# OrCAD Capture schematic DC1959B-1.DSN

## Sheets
1 PAGE2: size A; title: ULTRALOW NOISE & SPURIOUS FRACTIONAL-N; rev: 1; note: DEMO CIRCUIT 1959B
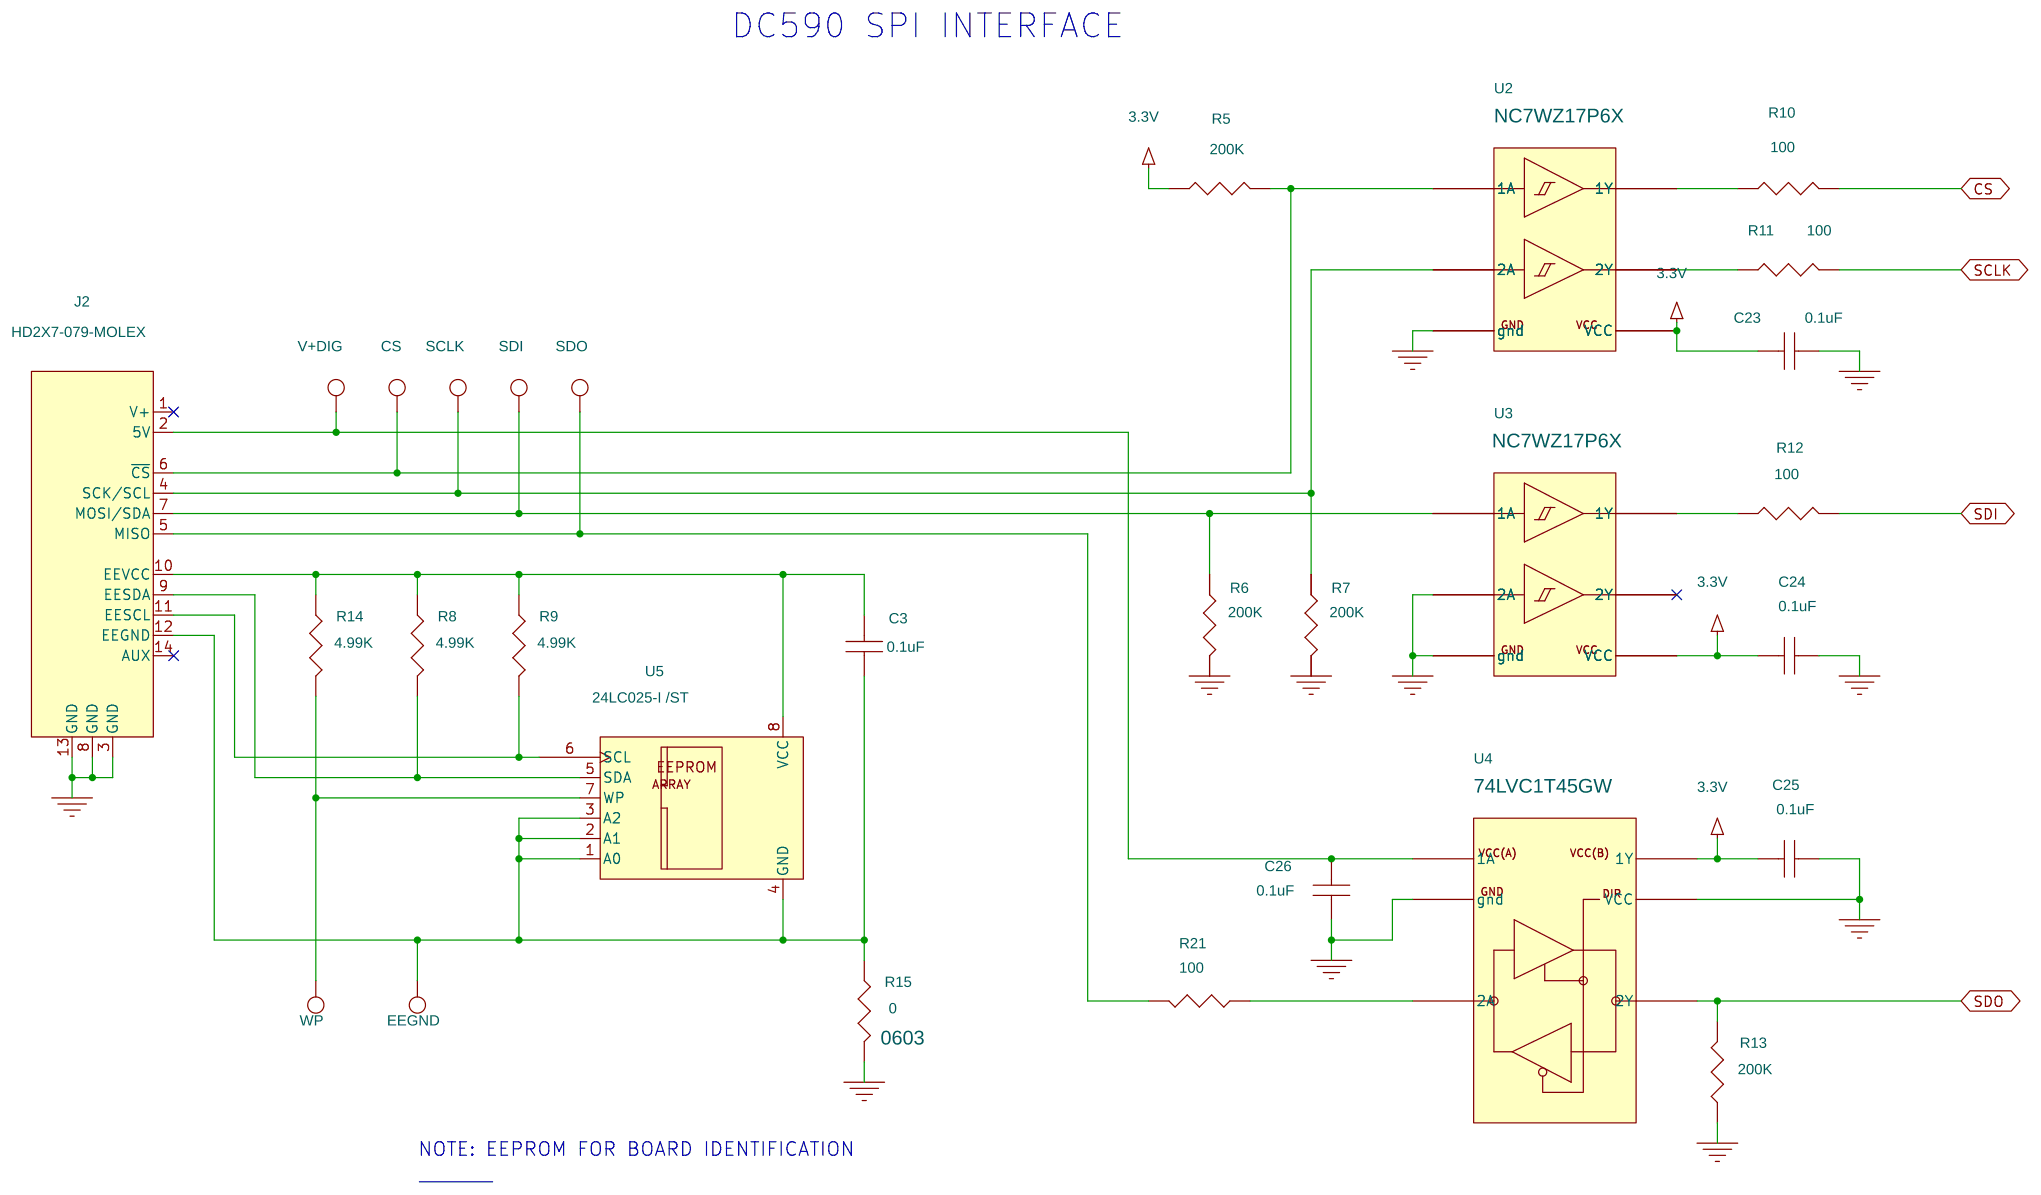
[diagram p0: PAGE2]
2 PAGE1: size Custom
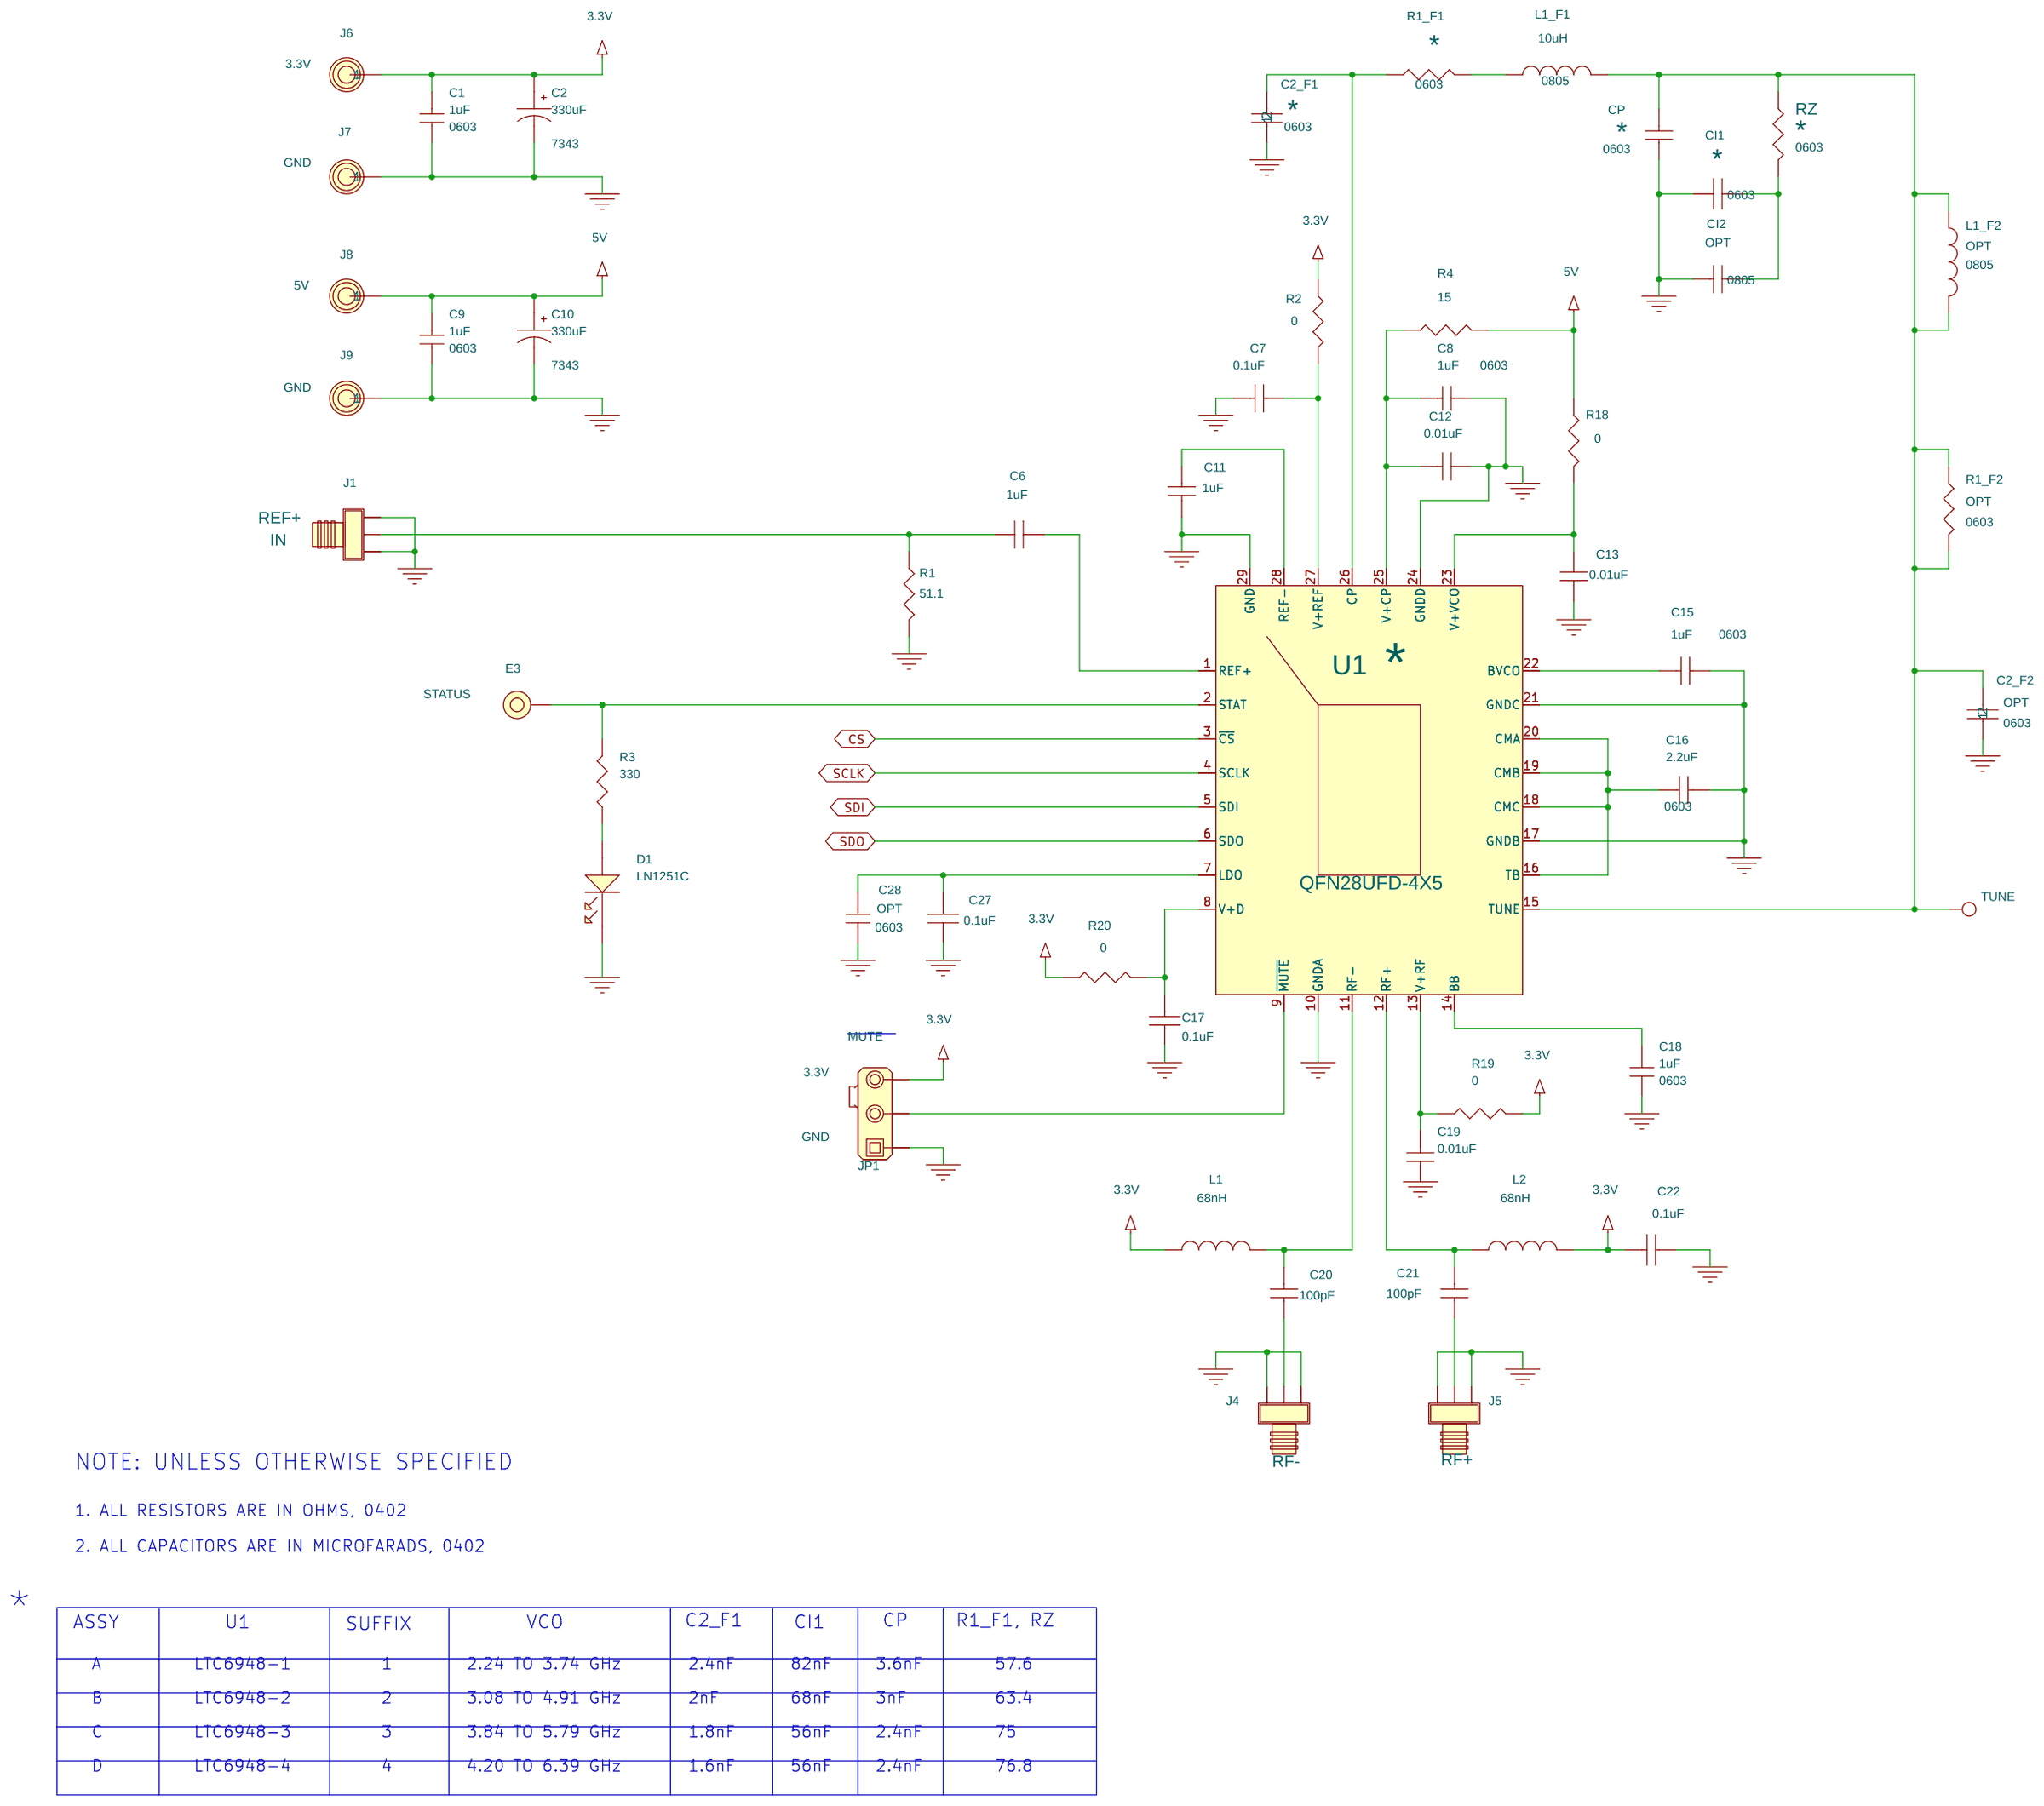
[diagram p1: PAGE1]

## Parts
sheet PAGE1
C1  1uF  [0603]
C2  330uF  [7343]
C2_F1  *  [0603]
C2_F2  OPT  [0603]
C6  1uF  [0402]
C7  0.1uF  [0402]
C8  1uF  [0603]
C9  1uF  [0603]
C10  330uF  [7343]
C11  1uF  [0402]
C12  0.01uF  [0402]
C13  0.01uF  [0402]
C15  1uF  [0603]
C16  2.2uF  [0603]
C17  0.1uF  [0402]
C18  1uF  [0603]
C19  0.01uF  [0402]
C20  100pF  [0402]
C21  100pF  [0402]
C22  0.1uF  [0402]
C27  0.1uF  [0402]
C28  OPT  [0603]
CI1  *  [0603]
CI2  OPT  [0805]
CP  *  [0603]
D1  LN1251C  [LED-LN1251C-RED]
E3  MILLMAX-90  [MILL-MAX-2501]
J1  142-0701-851  [CON-SMA-R]
J4  142-0701-851  [CON-SMA-R]
J5  142-0701-851  [CON-SMA-R]
J6  KEY-575-4  [KEY-575]
J7  KEY-575-4  [KEY-575]
J8  KEY-575-4  [KEY-575]
J9  KEY-575-4  [KEY-575]
JP1  HD1X3-079  [HD1X3-079]
L1  68nH  [0402]
L1_F1  10uH  [0805]
L1_F2  OPT  [0805]
L2  68nH  [0402]
R1  51.1  [0402]
R1_F1  *  [0603]
R1_F2  OPT  [0603]
R2  0  [0402]
R3  330  [0402]
R4  15  [0402]
R18  0  [0402]
R19  0  [0402]
R20  0  [0402]
RZ  *  [0603]
TUNE  TESTPAD-SMD/050SQ/NON/ECO  [TESTPAD-SMD/050SQ/NON/ECO]
U1  *  [QFN28UFD-4X5]
XJP1  2mm Ctrs.
sheet PAGE2
C3  0.1uF  [0402]
C23  0.1uF  [0402]
C24  0.1uF  [0402]
C25  0.1uF  [0402]
C26  0.1uF  [0402]
CS  TESTPAD-SMD/050SQ/NON/ECO  [TESTPAD-SMD/050SQ/NON/ECO]
EEGND  TESTPAD-SMD/050SQ/NON/ECO  [TESTPAD-SMD/050SQ/NON/ECO]
J2  HD2X7-079-MOLEX  [HD2X7-079-MOLEX]
R5  200K  [0402]
R6  200K  [0402]
R7  200K  [0402]
R8  4.99K  [0402]
R9  4.99K  [0402]
R10  100  [0402]
R11  100  [0402]
R12  100  [0402]
R13  200K  [0402]
R14  4.99K  [0402]
R15  0  [0603]
R21  100  [0402]
SCLK  TESTPAD-SMD/050SQ/NON/ECO  [TESTPAD-SMD/050SQ/NON/ECO]
SDI  TESTPAD-SMD/050SQ/NON/ECO  [TESTPAD-SMD/050SQ/NON/ECO]
SDO  TESTPAD-SMD/050SQ/NON/ECO  [TESTPAD-SMD/050SQ/NON/ECO]
U2  NC7WZ17P6X  [SC70-6]
U3  NC7WZ17P6X  [SC70-6]
U4  74LVC1T45GW  [SOT363]
U5  24LC025-I /ST  [TSSOP8]
V+DIG  TESTPAD-SMD/050SQ/NON/ECO  [TESTPAD-SMD/050SQ/NON/ECO]
WP  TESTPAD-SMD/050SQ/NON/ECO  [TESTPAD-SMD/050SQ/NON/ECO]

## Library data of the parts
C1 C8 C9 C18 C28 = EMK212BJ105MG_0: 2nd Part Field: 10%; 4th Part Field: TDK; 5th Part Field: C2012X7R1C105K
C2 C10 = t510x337k010as
C2_F1 = CAP_NP_1: CAP, 0603 TBD; 1st Part Field: 50V; 2nd Part Field: 10%; 3rd Part Field: X7R; 4th Part Field: AVX; 5th Part Field: 12065C104KATM; 7th Part Field: CAP.,; OPT: TBD; Part Number: TBD
C2_F2 = CAP_NP: CAP, 0603 TBD; 1st Part Field: 50V; 2nd Part Field: 10%; 3rd Part Field: X7R; 4th Part Field: AVX; 5th Part Field: 12065C104KATM; 7th Part Field: CAP.,; Part Number: TBD
C6 C11 = 04025C471KAT2A_0
C7 C12 C13 C15 C19 = 0402YC103KAT2A_0
C16 = EMK212BJ225MG_0
C3 C17 C22-C27 = 0402ZD104KAT2A
C20 C21 = 04025A101JAT2A_1: 2nd Part Field: 5%
CI1 = 06035C2232JAT2A: OPT: TBD
CI2 = GRM2195C1H682JA01D: OPT: TBD
CP = GRM1885C1H272JA01D: OPT: TBD
D1 = LED_1: 10uH: <10uH>
E3 = MillMax-2501-2: 9th Part Field: STATUS; STATUS: 1.6V, 1.8V, 2.0V OR 2.5V @ 15A; label: STATUS
J1 = SMA-CON-R: 1st Part Field: REF+; 2nd Part Field: IN
J4 = SMA-CON-R: 1st Part Field: RF-
J5 = SMA-CON-R: 1st Part Field: RF+
J6 = Keystone-575-4_0: 9th Part Field: 3.3V; label: 3.3V
J7 J9 = Keystone-575-4_0: 9th Part Field: GND; label: GND
J8 = Keystone-575-4_0: 9th Part Field: 5V; label: 5V
JP1 = Samtec_TMM-103-02-L-S: 11th Part Field: 3.3V; 12th Part Field: MUTE; 9th Part Field: GND
L1 L2 = 0402HPH-68NXJL
L1_F1 = INDUCTOR: IND, 0805 TBD; COMPFIXED: CDR6D28MNNP-7R7NC; COMPGROUP: SUMIDA; OPT: TBD; Part Number: TBD
L1_F2 = INDUCTOR: IND, 0805 TBD; COMPFIXED: CDR6D28MNNP-7R7NC; COMPGROUP: SUMIDA; Part Number: TBD
R1 R2 R18-R20 = CRCW040251R1FKED
R1_F1 = RESISTOR: RES, 0603 TBD; 1st Part Field: 1/8W; 2nd Part Field: 5%; 3rd Part Field: CHIP; 4th Part Field: PHILLIPS; 5th Part Field: 9C12063A51R0JM; 7th Part Field: RES.,; OPT: TBD; Part Number: TBD
R1_F2 = RESISTOR: RES, 0603 TBD; 1st Part Field: 1/8W; 2nd Part Field: 5%; 3rd Part Field: CHIP; 4th Part Field: PHILLIPS; 5th Part Field: 9C12063A51R0JM; 7th Part Field: RES.,; Part Number: TBD
R3 = CRCW0402330RJNED
R4 = CRCW040215R0JNED
RZ = NRC06F4530TRF: OPT: TBD
CS EEGND SCLK SDI SDO TUNE V+DIG WP = E-SMT-060_2
U1 = LTC6948IUFD-QFN28UFD-4X5: IC,; 4th Part Field: LINEAR TECH.; 7th Part Field: I.C.,; Part Number: LINEAR TECH. LTC6947IUFD
XJP1 = Samtec_2SN-BK-G
J2 = HD2X7-079-MOLEX
R5-R7 R13 R15 R21 = CRCW0402200KJNED
R8 R9 R14 = RESISTOR
R10-R12 = CRCW0402100RJNED
U2 U3 = NC7WZ17P6X_SGL_PAK_0
U4 = 74LVC1T45GW_SGL_PAK_0
U5 = 24LC025-I_ST

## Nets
3.3V: C1.2 C2.1 C22.2 C23.2 C24.2 C25.2 J6.1 JP1.3 L1.1 L2.2 R2.1 R5.2 R19.2 R20.1 U2.5(VCC) U3.5(VCC) U4.6(1Y)
5V: C9.2 C10.1 J8.1 R4.2 R18.1
GND: C1.1 C2.2 C2_F1.1 C2_F2.1 C7.2 C8.1 C9.1 C10.2 C11.2 C12.1 C13.2 C15.1 C16.2 C17.1 C18.1 C19.1 C22.1 C23.1 C24.1 C25.1 C26.1 C27.1 C28.1 CI1.1 CI2.1 CP.1 D1.2 J1.2 J1.3 J1.4 J1.5 J2.3(GND) J2.8(GND) J2.13(GND) J4.2 J4.3 J4.4 J4.5 J5.2 J5.3 J5.4 J5.5 J7.1 J9.1 JP1.1 R1.2 R6.2 R7.2 R13.1 R15.2 U1.10(GNDA) U1.17(GNDB) U1.21(GNDC) U1.24(GNDD) U1.29(GND) U2.2(gnd) U3.2(gnd) U3.3(2A) U4.2(gnd) U4.5(VCC)
CS: R10.2 U1.3(~{CS})
SCLK: R11.2 U1.4(SCLK)
SDI: R12.2 U1.5(SDI)
SDO: R13.2 U1.6(SDO) U4.4(2Y)
N163483: C8.2 C12.2 R4.1 U1.25(V+CP)
N163507: C20.1 J4.1
N163561: C21.1 J5.1
N163593: E3.1 R3.2 U1.2(STAT)
N163629: C11.1 U1.28(REF-)
N163649: C15.2 U1.22(BVCO)
N163763: C18.2 U1.14(BB)
N163801: JP1.2 U1.9(~{MUTE})
N163833: C16.1 U1.16(TB) U1.18(CMC) U1.19(CMB) U1.20(CMA)
N164033: C2_F1.2 R1_F1.1 U1.26(CP)
N164067: C6.1 J1.1 R1.1
N164097: C6.2 U1.1(REF+)
N164167: D1.1 R3.1
N164483: C20.2 L1.2 U1.11(RF-)
N164683: C21.2 L2.1 U1.12(RF+)
N164755: C7.1 R2.2 U1.27(V+REF)
N164763: C2_F2.2 CP.2 L1_F1.1 L1_F2.1 L1_F2.2 R1_F2.1 R1_F2.2 RZ.1 TUNE.1 U1.15(TUNE)
N164787: CI1.2 CI2.2 RZ.2
N166527: C3.2 J2.10(EEVCC) R8.2 R9.2 R14.2 U5.8(VCC)
N166531: J2.11(EESCL) R9.1 U5.6(SCL)
N166543: J2.9(EESDA) R8.1 U5.5(SDA)
N166561: C3.1 EEGND.1 J2.12(EEGND) R15.1 U5.1(A0) U5.2(A1) U5.3(A2) U5.4(GND)
N166573: J2.5(MISO) R21.2 SDO.1
N166597: J2.7(MOSI/SDA) R6.1 SDI.1 U3.1(1A)
N166627: J2.4(SCK/SCL) R7.1 SCLK.1 U2.3(2A)
N166635: CS.1 J2.6(~{CS}) R5.1 U2.1(1A)
N166643: C26.2 J2.2(5V) U4.1(1A) V+DIG.1
N166651: R14.1 U5.7(WP) WP.1
N166941: R12.1 U3.6(1Y)
N167357: R11.1 U2.4(2Y)
N167361: R10.1 U2.6(1Y)
N16713684: C19.2 R19.1 U1.13(V+RF)
N16728762: C17.2 R20.2 U1.8(V+D)
N16733294: C13.1 R18.2 U1.23(V+VCO)
N16892135: L1_F1.2 R1_F1.2
N16909871: C27.2 C28.2 U1.7(LDO)
N17005904: R21.1 U4.3(2A)

Not connected (* = marked no-connect by the designer): J2 1(V+)* 14(AUX)*; U3 4(2Y)*

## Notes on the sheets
sheet 1
- DC590 SPI INTERFACE
- NOTE: EEPROM FOR BOARD IDENTIFICATION
sheet 2
- NOTE: UNLESS OTHERWISE SPECIFIED
- 1. ALL RESISTORS ARE IN OHMS, 0402
- 2. ALL CAPACITORS ARE IN MICROFARADS, 0402
- *
- ASSY
- U1
- SUFFIX
- VCO
- C2_F1
- CI1
- CP
- R1_F1, RZ
- A
- LTC6948-1
- 1
- 2.24 TO 3.74 GHz
- 2.4nF
- 82nF
- 3.6nF
- 57.6
- B
- LTC6948-2
- 2
- 3.08 TO 4.91 GHz
- 2nF
- 68nF
- 3nF
- 63.4
- C
- LTC6948-3
- 3
- 3.84 TO 5.79 GHz
- 1.8nF
- 56nF
- 2.4nF
- 75
- D
- LTC6948-4
- 4
- 4.20 TO 6.39 GHz
- 1.6nF
- 56nF
- 2.4nF
- 76.8
